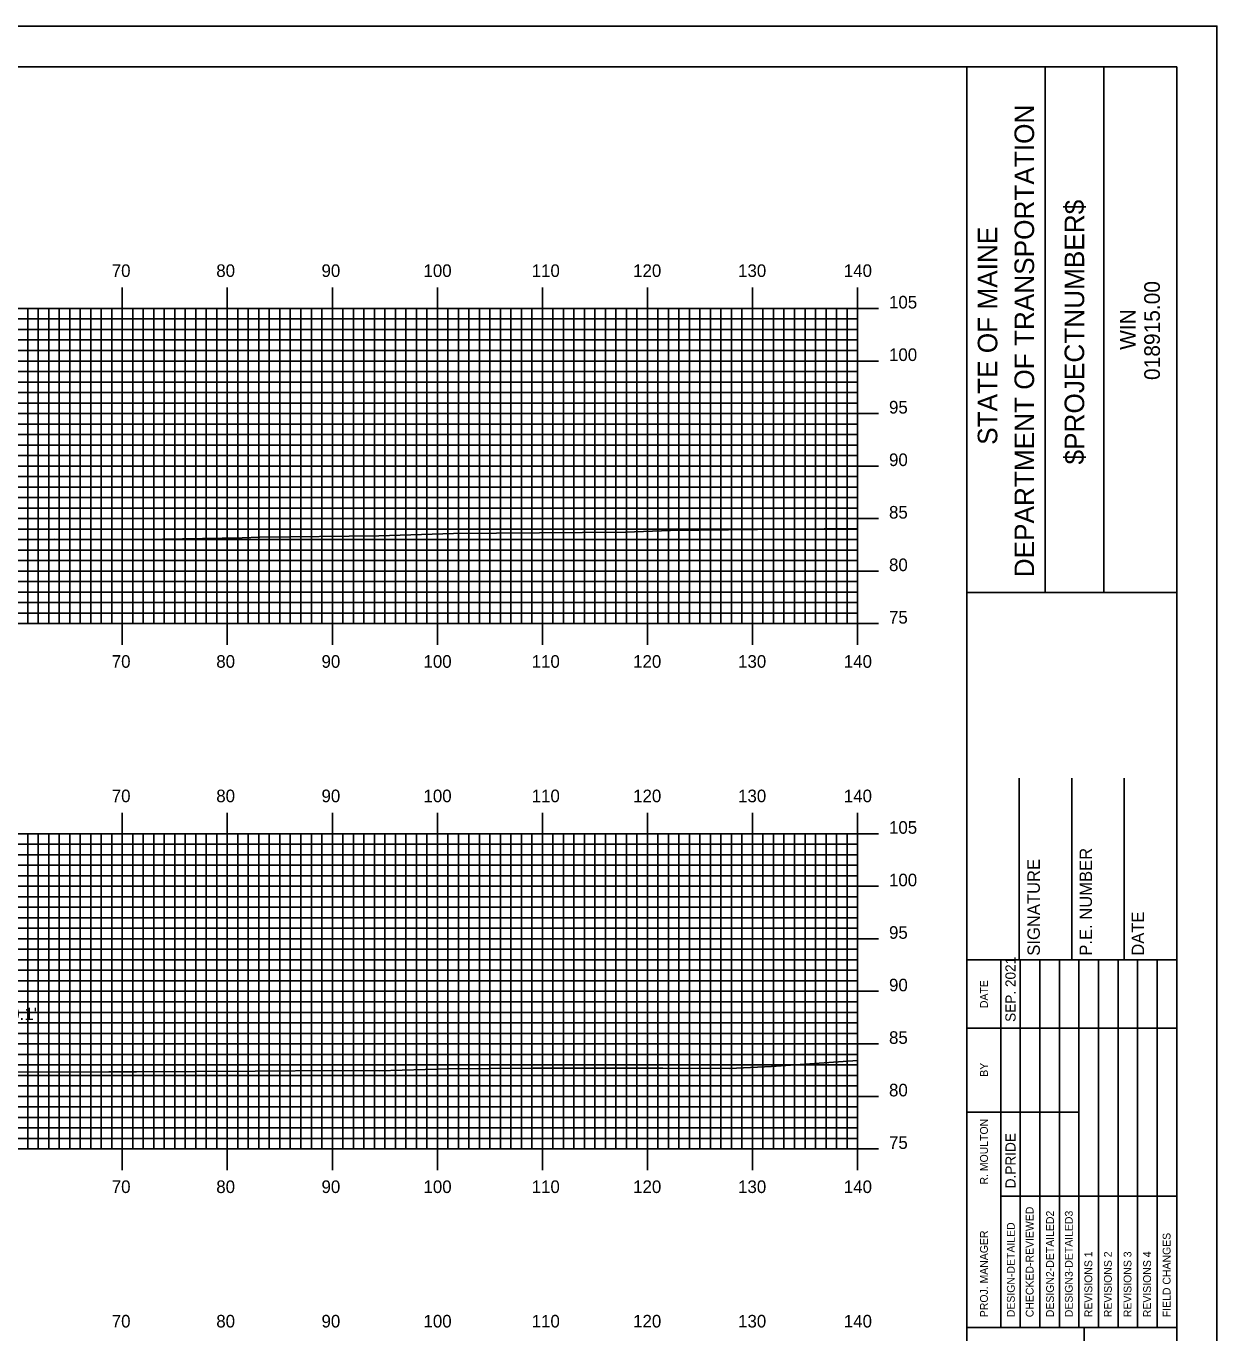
# Model space of a CAD drawing. Extents: x 1757462 to 1757806, y 442591 to 442811.
# Drawn here: x 1757689 to 1757802.3, y 442686.2 to 442810.5 of the extents above; entities that cross this region are included whole.
import ezdxf

# ---------------------------------------------------------------- set-up
doc = ezdxf.new("R2010")
doc.units = 0
for name, color, linetype in [('BORDER', 7, 'Continuous'), ('D_Text_Standard', 7, 'Continuous'), ('H_V ANNOTATION', 7, 'Continuous'), ('MAJOR', 7, 'Continuous'), ('MINOR', 7, 'Continuous'), ('PLOT BOUNDARY', 7, 'Continuous'), ('S_Roadway_Centerline', 7, 'Continuous')]:
    doc.layers.add(name, color=color, linetype=linetype)

msp = doc.modelspace()

# ---------------------------------------------------------------- linework, layer by layer
at = {"layer": 'BORDER'}
for p, q in [((1757778.51, 442596.67), (1757778.51, 442806.67)), ((1757785.97, 442756.66), (1757785.97, 442806.66)), ((1757791.56, 442756.66), (1757791.56, 442806.66)), ((1757778.51, 442756.65), (1757798.51, 442756.65)), ((1757783.51, 442721.67), (1757783.51, 442738.97)), ((1757788.51, 442721.67), (1757788.51, 442738.97)), ((1757793.51, 442721.67), (1757793.51, 442738.97)), ((1757778.51, 442721.67), (1757798.51, 442721.67)), ((1757778.51, 442686.67), (1757798.51, 442686.67)), ((1757789.69, 442616.67), (1757789.69, 442686.67))]:
    msp.add_line(p, q, dxfattribs=at)
msp.add_lwpolyline([(1757478.51, 442596.67), (1757798.51, 442596.67), (1757798.51, 442806.67), (1757478.51, 442806.67)], close=True, dxfattribs=at)
for points in [[(1757781.74, 442715.17), (1757781.74, 442721.67)], [(1757783.6, 442686.68), (1757783.6, 442721.67)], [(1757785.47, 442721.67), (1757785.47, 442686.68)], [(1757787.33, 442686.68), (1757787.33, 442721.67)], [(1757789.19, 442686.68), (1757789.19, 442721.67)], [(1757791.06, 442686.68), (1757791.06, 442721.67)], [(1757792.92, 442686.68), (1757792.92, 442721.67)], [(1757794.78, 442686.68), (1757794.78, 442721.67)], [(1757796.65, 442686.68), (1757796.65, 442721.67)], [(1757781.74, 442686.68), (1757781.74, 442720.26)], [(1757778.51, 442715.17), (1757798.51, 442715.17)], [(1757778.51, 442707.17), (1757781.74, 442707.17)], [(1757781.74, 442707.17), (1757789.19, 442707.17)], [(1757781.74, 442699.17), (1757798.51, 442699.17)]]:
    msp.add_lwpolyline(points, dxfattribs=at)
at = {"layer": 'MAJOR'}
for p, q in [((1757698.11, 442785.67), (1757698.11, 442783.67)), ((1757708.11, 442785.67), (1757708.11, 442783.67)), ((1757718.11, 442785.67), (1757718.11, 442783.67)), ((1757728.11, 442785.67), (1757728.11, 442783.67)), ((1757738.11, 442785.67), (1757738.11, 442783.67)), ((1757748.11, 442785.67), (1757748.11, 442783.67)), ((1757758.11, 442785.67), (1757758.11, 442783.67)), ((1757768.11, 442785.67), (1757768.11, 442783.67)), ((1757488.11, 442783.67), (1757768.11, 442783.67)), ((1757488.11, 442783.67), (1757768.11, 442783.67)), ((1757698.11, 442753.67), (1757698.11, 442783.67)), ((1757708.11, 442753.67), (1757708.11, 442783.67)), ((1757718.11, 442753.67), (1757718.11, 442783.67)), ((1757728.11, 442753.67), (1757728.11, 442783.67)), ((1757738.11, 442753.67), (1757738.11, 442783.67)), ((1757748.11, 442753.67), (1757748.11, 442783.67)), ((1757758.11, 442753.67), (1757758.11, 442783.67)), ((1757770.11, 442783.67), (1757766.11, 442783.67)), ((1757768.11, 442753.67), (1757768.11, 442783.67)), ((1757768.11, 442753.67), (1757768.11, 442783.67)), ((1757488.11, 442778.67), (1757768.11, 442778.67)), ((1757770.11, 442778.67), (1757766.11, 442778.67)), ((1757488.11, 442773.67), (1757768.11, 442773.67)), ((1757770.11, 442773.67), (1757766.11, 442773.67)), ((1757488.11, 442768.67), (1757768.11, 442768.67)), ((1757770.11, 442768.67), (1757766.11, 442768.67)), ((1757488.11, 442763.67), (1757768.11, 442763.67)), ((1757770.11, 442763.67), (1757766.11, 442763.67)), ((1757488.11, 442758.67), (1757768.11, 442758.67)), ((1757770.11, 442758.67), (1757766.11, 442758.67)), ((1757488.11, 442753.67), (1757768.11, 442753.67)), ((1757488.11, 442753.67), (1757768.11, 442753.67)), ((1757698.11, 442751.66), (1757698.11, 442753.67)), ((1757708.11, 442751.66), (1757708.11, 442753.67)), ((1757718.11, 442751.66), (1757718.11, 442753.67)), ((1757728.11, 442751.66), (1757728.11, 442753.67)), ((1757738.11, 442751.66), (1757738.11, 442753.67)), ((1757748.11, 442751.66), (1757748.11, 442753.67)), ((1757758.11, 442751.66), (1757758.11, 442753.67)), ((1757770.11, 442753.67), (1757766.11, 442753.67)), ((1757768.11, 442751.66), (1757768.11, 442753.67)), ((1757698.11, 442735.67), (1757698.11, 442733.67)), ((1757708.11, 442735.67), (1757708.11, 442733.67)), ((1757718.11, 442735.67), (1757718.11, 442733.67)), ((1757728.11, 442735.67), (1757728.11, 442733.67)), ((1757738.11, 442735.67), (1757738.11, 442733.67)), ((1757748.11, 442735.67), (1757748.11, 442733.67)), ((1757758.11, 442735.67), (1757758.11, 442733.67)), ((1757768.11, 442735.67), (1757768.11, 442733.67)), ((1757488.11, 442733.67), (1757768.11, 442733.67)), ((1757488.11, 442733.67), (1757768.11, 442733.67)), ((1757698.11, 442703.67), (1757698.11, 442733.67)), ((1757708.11, 442703.67), (1757708.11, 442733.67)), ((1757718.11, 442703.67), (1757718.11, 442733.67)), ((1757728.11, 442703.67), (1757728.11, 442733.67)), ((1757738.11, 442703.67), (1757738.11, 442733.67)), ((1757748.11, 442703.67), (1757748.11, 442733.67)), ((1757758.11, 442703.67), (1757758.11, 442733.67)), ((1757770.11, 442733.67), (1757766.11, 442733.67)), ((1757768.11, 442703.67), (1757768.11, 442733.67)), ((1757768.11, 442703.67), (1757768.11, 442733.67)), ((1757488.11, 442728.67), (1757768.11, 442728.67)), ((1757770.11, 442728.67), (1757766.11, 442728.67)), ((1757488.11, 442723.67), (1757768.11, 442723.67)), ((1757770.11, 442723.67), (1757766.11, 442723.67)), ((1757488.11, 442718.67), (1757768.11, 442718.67)), ((1757770.11, 442718.67), (1757766.11, 442718.67)), ((1757488.11, 442713.67), (1757768.11, 442713.67)), ((1757770.11, 442713.67), (1757766.11, 442713.67)), ((1757488.11, 442708.67), (1757768.11, 442708.67)), ((1757770.11, 442708.67), (1757766.11, 442708.67)), ((1757488.11, 442703.67), (1757768.11, 442703.67)), ((1757488.11, 442703.67), (1757768.11, 442703.67)), ((1757698.11, 442701.66), (1757698.11, 442703.67)), ((1757708.11, 442701.66), (1757708.11, 442703.67)), ((1757718.11, 442701.66), (1757718.11, 442703.67)), ((1757728.11, 442701.66), (1757728.11, 442703.67)), ((1757738.11, 442701.66), (1757738.11, 442703.67)), ((1757748.11, 442701.66), (1757748.11, 442703.67)), ((1757758.11, 442701.66), (1757758.11, 442703.67)), ((1757770.11, 442703.67), (1757766.11, 442703.67)), ((1757768.11, 442701.66), (1757768.11, 442703.67))]:
    msp.add_line(p, q, dxfattribs=at)
at = {"layer": 'MINOR'}
for p, q in [((1757689.11, 442753.67), (1757689.11, 442783.67)), ((1757690.11, 442753.67), (1757690.11, 442783.67)), ((1757691.11, 442753.67), (1757691.11, 442783.67)), ((1757692.11, 442753.67), (1757692.11, 442783.67)), ((1757693.11, 442753.67), (1757693.11, 442783.67)), ((1757694.11, 442753.67), (1757694.11, 442783.67)), ((1757695.11, 442753.67), (1757695.11, 442783.67)), ((1757696.11, 442753.67), (1757696.11, 442783.67)), ((1757697.11, 442753.67), (1757697.11, 442783.67)), ((1757699.11, 442753.67), (1757699.11, 442783.67)), ((1757700.11, 442753.67), (1757700.11, 442783.67)), ((1757701.11, 442753.67), (1757701.11, 442783.67)), ((1757702.11, 442753.67), (1757702.11, 442783.67)), ((1757703.11, 442753.67), (1757703.11, 442783.67)), ((1757704.11, 442753.67), (1757704.11, 442783.67)), ((1757705.11, 442753.67), (1757705.11, 442783.67)), ((1757706.11, 442753.67), (1757706.11, 442783.67)), ((1757707.11, 442753.67), (1757707.11, 442783.67)), ((1757709.11, 442753.67), (1757709.11, 442783.67)), ((1757710.11, 442753.67), (1757710.11, 442783.67)), ((1757711.11, 442753.67), (1757711.11, 442783.67)), ((1757712.11, 442753.67), (1757712.11, 442783.67)), ((1757713.11, 442753.67), (1757713.11, 442783.67)), ((1757714.11, 442753.67), (1757714.11, 442783.67)), ((1757715.11, 442753.67), (1757715.11, 442783.67)), ((1757716.11, 442753.67), (1757716.11, 442783.67)), ((1757717.11, 442753.67), (1757717.11, 442783.67)), ((1757719.11, 442753.67), (1757719.11, 442783.67)), ((1757720.11, 442753.67), (1757720.11, 442783.67)), ((1757721.11, 442753.67), (1757721.11, 442783.67)), ((1757722.11, 442753.67), (1757722.11, 442783.67)), ((1757723.11, 442753.67), (1757723.11, 442783.67)), ((1757724.11, 442753.67), (1757724.11, 442783.67)), ((1757725.11, 442753.67), (1757725.11, 442783.67)), ((1757726.11, 442753.67), (1757726.11, 442783.67)), ((1757727.11, 442753.67), (1757727.11, 442783.67)), ((1757729.11, 442753.67), (1757729.11, 442783.67)), ((1757730.11, 442753.67), (1757730.11, 442783.67)), ((1757731.11, 442753.67), (1757731.11, 442783.67)), ((1757732.11, 442753.67), (1757732.11, 442783.67)), ((1757733.11, 442753.67), (1757733.11, 442783.67)), ((1757734.11, 442753.67), (1757734.11, 442783.67)), ((1757735.11, 442753.67), (1757735.11, 442783.67)), ((1757736.11, 442753.67), (1757736.11, 442783.67)), ((1757737.11, 442753.67), (1757737.11, 442783.67)), ((1757739.11, 442753.67), (1757739.11, 442783.67)), ((1757740.11, 442753.67), (1757740.11, 442783.67)), ((1757741.11, 442753.67), (1757741.11, 442783.67)), ((1757742.11, 442753.67), (1757742.11, 442783.67)), ((1757743.11, 442753.67), (1757743.11, 442783.67)), ((1757744.11, 442753.67), (1757744.11, 442783.67)), ((1757745.11, 442753.67), (1757745.11, 442783.67)), ((1757746.11, 442753.67), (1757746.11, 442783.67)), ((1757747.11, 442753.67), (1757747.11, 442783.67)), ((1757749.11, 442753.67), (1757749.11, 442783.67)), ((1757750.11, 442753.67), (1757750.11, 442783.67)), ((1757751.11, 442753.67), (1757751.11, 442783.67)), ((1757752.11, 442753.67), (1757752.11, 442783.67)), ((1757753.11, 442753.67), (1757753.11, 442783.67)), ((1757754.11, 442753.67), (1757754.11, 442783.67)), ((1757755.11, 442753.67), (1757755.11, 442783.67)), ((1757756.11, 442753.67), (1757756.11, 442783.67)), ((1757757.11, 442753.67), (1757757.11, 442783.67)), ((1757759.11, 442753.67), (1757759.11, 442783.67)), ((1757760.11, 442753.67), (1757760.11, 442783.67)), ((1757761.11, 442753.67), (1757761.11, 442783.67)), ((1757762.11, 442753.67), (1757762.11, 442783.67)), ((1757763.11, 442753.67), (1757763.11, 442783.67)), ((1757764.11, 442753.67), (1757764.11, 442783.67)), ((1757765.11, 442753.67), (1757765.11, 442783.67)), ((1757766.11, 442753.67), (1757766.11, 442783.67)), ((1757767.11, 442753.67), (1757767.11, 442783.67)), ((1757488.11, 442782.67), (1757768.11, 442782.67)), ((1757768.11, 442782.67), (1757766.11, 442782.67)), ((1757488.11, 442781.67), (1757768.11, 442781.67)), ((1757768.11, 442781.67), (1757766.11, 442781.67)), ((1757488.11, 442780.67), (1757768.11, 442780.67)), ((1757768.11, 442780.67), (1757766.11, 442780.67)), ((1757488.11, 442779.67), (1757768.11, 442779.67)), ((1757768.11, 442779.67), (1757766.11, 442779.67)), ((1757488.11, 442777.67), (1757768.11, 442777.67)), ((1757768.11, 442777.67), (1757766.11, 442777.67)), ((1757488.11, 442776.67), (1757768.11, 442776.67)), ((1757768.11, 442776.67), (1757766.11, 442776.67)), ((1757488.11, 442775.67), (1757768.11, 442775.67)), ((1757768.11, 442775.67), (1757766.11, 442775.67)), ((1757488.11, 442774.67), (1757768.11, 442774.67)), ((1757768.11, 442774.67), (1757766.11, 442774.67)), ((1757488.11, 442772.67), (1757768.11, 442772.67)), ((1757768.11, 442772.67), (1757766.11, 442772.67)), ((1757488.11, 442771.67), (1757768.11, 442771.67)), ((1757768.11, 442771.67), (1757766.11, 442771.67)), ((1757488.11, 442770.67), (1757768.11, 442770.67)), ((1757768.11, 442770.67), (1757766.11, 442770.67)), ((1757488.11, 442769.67), (1757768.11, 442769.67)), ((1757768.11, 442769.67), (1757766.11, 442769.67)), ((1757488.11, 442767.67), (1757768.11, 442767.67)), ((1757768.11, 442767.67), (1757766.11, 442767.67)), ((1757488.11, 442766.67), (1757768.11, 442766.67)), ((1757768.11, 442766.67), (1757766.11, 442766.67)), ((1757488.11, 442765.67), (1757768.11, 442765.67)), ((1757768.11, 442765.67), (1757766.11, 442765.67)), ((1757488.11, 442764.67), (1757768.11, 442764.67)), ((1757768.11, 442764.67), (1757766.11, 442764.67)), ((1757488.11, 442762.67), (1757768.11, 442762.67)), ((1757768.11, 442762.67), (1757766.11, 442762.67)), ((1757488.11, 442761.67), (1757768.11, 442761.67)), ((1757768.11, 442761.67), (1757766.11, 442761.67)), ((1757488.11, 442760.67), (1757768.11, 442760.67)), ((1757768.11, 442760.67), (1757766.11, 442760.67)), ((1757488.11, 442759.67), (1757768.11, 442759.67)), ((1757768.11, 442759.67), (1757766.11, 442759.67)), ((1757488.11, 442757.67), (1757768.11, 442757.67)), ((1757768.11, 442757.67), (1757766.11, 442757.67)), ((1757488.11, 442756.67), (1757768.11, 442756.67)), ((1757768.11, 442756.67), (1757766.11, 442756.67)), ((1757488.11, 442755.67), (1757768.11, 442755.67)), ((1757768.11, 442755.67), (1757766.11, 442755.67)), ((1757488.11, 442754.67), (1757768.11, 442754.67)), ((1757768.11, 442754.67), (1757766.11, 442754.67)), ((1757488.11, 442732.67), (1757768.11, 442732.67)), ((1757689.11, 442703.67), (1757689.11, 442733.67)), ((1757690.11, 442703.67), (1757690.11, 442733.67)), ((1757691.11, 442703.67), (1757691.11, 442733.67)), ((1757692.11, 442703.67), (1757692.11, 442733.67)), ((1757693.11, 442703.67), (1757693.11, 442733.67)), ((1757694.11, 442703.67), (1757694.11, 442733.67)), ((1757695.11, 442703.67), (1757695.11, 442733.67)), ((1757696.11, 442703.67), (1757696.11, 442733.67)), ((1757697.11, 442703.67), (1757697.11, 442733.67)), ((1757699.11, 442703.67), (1757699.11, 442733.67)), ((1757700.11, 442703.67), (1757700.11, 442733.67)), ((1757701.11, 442703.67), (1757701.11, 442733.67)), ((1757702.11, 442703.67), (1757702.11, 442733.67)), ((1757703.11, 442703.67), (1757703.11, 442733.67)), ((1757704.11, 442703.67), (1757704.11, 442733.67)), ((1757705.11, 442703.67), (1757705.11, 442733.67)), ((1757706.11, 442703.67), (1757706.11, 442733.67)), ((1757707.11, 442703.67), (1757707.11, 442733.67)), ((1757709.11, 442703.67), (1757709.11, 442733.67)), ((1757710.11, 442703.67), (1757710.11, 442733.67)), ((1757711.11, 442703.67), (1757711.11, 442733.67)), ((1757712.11, 442703.67), (1757712.11, 442733.67)), ((1757713.11, 442703.67), (1757713.11, 442733.67)), ((1757714.11, 442703.67), (1757714.11, 442733.67)), ((1757715.11, 442703.67), (1757715.11, 442733.67)), ((1757716.11, 442703.67), (1757716.11, 442733.67)), ((1757717.11, 442703.67), (1757717.11, 442733.67)), ((1757719.11, 442703.67), (1757719.11, 442733.67)), ((1757720.11, 442703.67), (1757720.11, 442733.67)), ((1757721.11, 442703.67), (1757721.11, 442733.67)), ((1757722.11, 442703.67), (1757722.11, 442733.67)), ((1757723.11, 442703.67), (1757723.11, 442733.67)), ((1757724.11, 442703.67), (1757724.11, 442733.67)), ((1757725.11, 442703.67), (1757725.11, 442733.67)), ((1757726.11, 442703.67), (1757726.11, 442733.67)), ((1757727.11, 442703.67), (1757727.11, 442733.67)), ((1757729.11, 442703.67), (1757729.11, 442733.67)), ((1757730.11, 442703.67), (1757730.11, 442733.67)), ((1757731.11, 442703.67), (1757731.11, 442733.67)), ((1757732.11, 442703.67), (1757732.11, 442733.67)), ((1757733.11, 442703.67), (1757733.11, 442733.67)), ((1757734.11, 442703.67), (1757734.11, 442733.67)), ((1757735.11, 442703.67), (1757735.11, 442733.67)), ((1757736.11, 442703.67), (1757736.11, 442733.67)), ((1757737.11, 442703.67), (1757737.11, 442733.67)), ((1757739.11, 442703.67), (1757739.11, 442733.67)), ((1757740.11, 442703.67), (1757740.11, 442733.67)), ((1757741.11, 442703.67), (1757741.11, 442733.67)), ((1757742.11, 442703.67), (1757742.11, 442733.67)), ((1757743.11, 442703.67), (1757743.11, 442733.67)), ((1757744.11, 442703.67), (1757744.11, 442733.67)), ((1757745.11, 442703.67), (1757745.11, 442733.67)), ((1757746.11, 442703.67), (1757746.11, 442733.67)), ((1757747.11, 442703.67), (1757747.11, 442733.67)), ((1757749.11, 442703.67), (1757749.11, 442733.67)), ((1757750.11, 442703.67), (1757750.11, 442733.67)), ((1757751.11, 442703.67), (1757751.11, 442733.67)), ((1757752.11, 442703.67), (1757752.11, 442733.67)), ((1757753.11, 442703.67), (1757753.11, 442733.67)), ((1757754.11, 442703.67), (1757754.11, 442733.67)), ((1757755.11, 442703.67), (1757755.11, 442733.67)), ((1757756.11, 442703.67), (1757756.11, 442733.67)), ((1757757.11, 442703.67), (1757757.11, 442733.67)), ((1757759.11, 442703.67), (1757759.11, 442733.67)), ((1757760.11, 442703.67), (1757760.11, 442733.67)), ((1757761.11, 442703.67), (1757761.11, 442733.67)), ((1757762.11, 442703.67), (1757762.11, 442733.67)), ((1757763.11, 442703.67), (1757763.11, 442733.67)), ((1757764.11, 442703.67), (1757764.11, 442733.67)), ((1757765.11, 442703.67), (1757765.11, 442733.67)), ((1757766.11, 442703.67), (1757766.11, 442733.67)), ((1757768.11, 442732.67), (1757766.11, 442732.67)), ((1757767.11, 442703.67), (1757767.11, 442733.67)), ((1757488.11, 442731.67), (1757768.11, 442731.67)), ((1757768.11, 442731.67), (1757766.11, 442731.67)), ((1757488.11, 442730.67), (1757768.11, 442730.67)), ((1757768.11, 442730.67), (1757766.11, 442730.67)), ((1757488.11, 442729.67), (1757768.11, 442729.67)), ((1757768.11, 442729.67), (1757766.11, 442729.67)), ((1757488.11, 442727.67), (1757768.11, 442727.67)), ((1757768.11, 442727.67), (1757766.11, 442727.67)), ((1757488.11, 442726.67), (1757768.11, 442726.67)), ((1757768.11, 442726.67), (1757766.11, 442726.67)), ((1757488.11, 442725.67), (1757768.11, 442725.67)), ((1757768.11, 442725.67), (1757766.11, 442725.67)), ((1757488.11, 442724.67), (1757768.11, 442724.67)), ((1757768.11, 442724.67), (1757766.11, 442724.67)), ((1757488.11, 442722.67), (1757768.11, 442722.67)), ((1757768.11, 442722.67), (1757766.11, 442722.67)), ((1757488.11, 442721.67), (1757768.11, 442721.67)), ((1757768.11, 442721.67), (1757766.11, 442721.67)), ((1757488.11, 442720.67), (1757768.11, 442720.67)), ((1757768.11, 442720.67), (1757766.11, 442720.67)), ((1757488.11, 442719.67), (1757768.11, 442719.67)), ((1757768.11, 442719.67), (1757766.11, 442719.67)), ((1757488.11, 442717.67), (1757768.11, 442717.67)), ((1757768.11, 442717.67), (1757766.11, 442717.67)), ((1757488.11, 442716.67), (1757768.11, 442716.67)), ((1757768.11, 442716.67), (1757766.11, 442716.67)), ((1757488.11, 442715.67), (1757768.11, 442715.67)), ((1757768.11, 442715.67), (1757766.11, 442715.67)), ((1757488.11, 442714.67), (1757768.11, 442714.67)), ((1757768.11, 442714.67), (1757766.11, 442714.67)), ((1757488.11, 442712.67), (1757768.11, 442712.67)), ((1757768.11, 442712.67), (1757766.11, 442712.67)), ((1757488.11, 442711.67), (1757768.11, 442711.67)), ((1757768.11, 442711.67), (1757766.11, 442711.67)), ((1757488.11, 442710.67), (1757768.11, 442710.67)), ((1757768.11, 442710.67), (1757766.11, 442710.67)), ((1757488.11, 442709.67), (1757768.11, 442709.67)), ((1757768.11, 442709.67), (1757766.11, 442709.67)), ((1757488.11, 442707.67), (1757768.11, 442707.67)), ((1757488.11, 442706.67), (1757768.11, 442706.67)), ((1757768.11, 442707.67), (1757766.11, 442707.67)), ((1757768.11, 442706.67), (1757766.11, 442706.67)), ((1757488.11, 442705.67), (1757768.11, 442705.67)), ((1757768.11, 442705.67), (1757766.11, 442705.67)), ((1757488.11, 442704.67), (1757768.11, 442704.67)), ((1757768.11, 442704.67), (1757766.11, 442704.67))]:
    msp.add_line(p, q, dxfattribs=at)
at = {"layer": 'PLOT BOUNDARY'}
msp.add_lwpolyline([(1757462.32, 442590.55), (1757802.32, 442590.55), (1757802.32, 442810.55), (1757462.32, 442810.55)], close=True, dxfattribs=at)
at = {"layer": 'S_Roadway_Centerline'}
for points in [[(1757679.59, 442761.55), (1757691.61, 442761.71), (1757698.15, 442761.64), (1757709.51, 442761.85), (1757711.21, 442761.89), (1757722.55, 442762.02), (1757729.66, 442762.25), (1757746.01, 442762.39), (1757750.29, 442762.53), (1757758.6, 442762.63), (1757768.11, 442762.74)], [(1757681.09, 442710.97), (1757696.82, 442711.01), (1757699.45, 442711), (1757710.76, 442711.08), (1757718.41, 442711.13), (1757722.56, 442711.11), (1757729.15, 442711.29), (1757737.23, 442711.36), (1757749.57, 442711.37), (1757755.92, 442711.33), (1757759.91, 442711.5), (1757768.11, 442712.09)]]:
    msp.add_lwpolyline(points, dxfattribs=at)

# ---------------------------------------------------------------- texts
at = {"layer": 'BORDER'}
for s, height, p in [('DEPARTMENT OF TRANSPORTATION', 1.8635, (1757784.92, 442758.08)), ('$PROJECTNUMBER$', 1.8635, (1757789.69, 442768.82)), ('STATE OF MAINE', 1.8635, (1757781.42, 442770.69)), ('018915.00', 1.491, (1757796.9, 442776.86)), ('WIN', 1.491, (1757794.58, 442779.73)), ('P.E. NUMBER', 1.1811, (1757790.43, 442722.06)), ('SIGNATURE', 1.181, (1757785.47, 442722.06)), ('DATE', 1.181, (1757795.39, 442722.06)), ('SEP. 2021', 0.969, (1757783.16, 442715.76)), ('DATE', 0.743, (1757780.52, 442717.08)), ('BY', 0.743, (1757780.52, 442710.54)), ('R. MOULTON', 0.745, (1757780.52, 442700.28)), ('D.PRIDE', 0.969, (1757783.16, 442699.92)), ('CHECKED-REVIEWED', 0.7455, (1757784.87, 442687.65)), ('DESIGN2-DETAILED2', 0.7455, (1757786.81, 442687.65)), ('DESIGN3-DETAILED3', 0.7455, (1757788.6, 442687.65)), ('DESIGN-DETAILED', 0.7455, (1757783.08, 442687.65)), ('PROJ. MANAGER', 0.7455, (1757780.52, 442687.65)), ('FIELD CHANGES', 0.7455, (1757797.91, 442687.65)), ('REVISIONS 1', 0.7455, (1757790.46, 442687.65)), ('REVISIONS 2', 0.7455, (1757792.32, 442687.65)), ('REVISIONS 3', 0.7455, (1757794.19, 442687.65)), ('REVISIONS 4', 0.7455, (1757796.05, 442687.65))]:
    msp.add_text(s, height=height, rotation=90, dxfattribs=at).set_placement(p)
at = {"layer": 'D_Text_Standard'}
msp.add_text("60.1'", height=1.2, dxfattribs=at).set_placement((1757686.55, 442715.93))
at = {"layer": 'H_V ANNOTATION'}
for s, p in [('70', (1757697.11, 442786.67)), ('80', (1757707.06, 442786.67)), ('90', (1757717.08, 442786.67)), ('100', (1757726.79, 442786.67)), ('110', (1757737.09, 442786.67)), ('120', (1757746.75, 442786.67)), ('130', (1757756.74, 442786.67)), ('140', (1757766.81, 442786.67)), ('105', (1757771.11, 442783.67)), ('100', (1757771.11, 442778.67)), ('95', (1757771.11, 442773.67)), ('90', (1757771.11, 442768.67)), ('85', (1757771.11, 442763.67)), ('80', (1757771.11, 442758.67)), ('75', (1757771.11, 442753.67)), ('70', (1757697.11, 442749.47)), ('80', (1757707.06, 442749.47)), ('90', (1757717.08, 442749.47)), ('100', (1757726.79, 442749.47)), ('110', (1757737.09, 442749.47)), ('120', (1757746.75, 442749.47)), ('130', (1757756.74, 442749.47)), ('140', (1757766.81, 442749.47)), ('70', (1757697.11, 442736.67)), ('80', (1757707.06, 442736.67)), ('90', (1757717.08, 442736.67)), ('100', (1757726.79, 442736.67)), ('110', (1757737.09, 442736.67)), ('120', (1757746.75, 442736.67)), ('130', (1757756.74, 442736.67)), ('140', (1757766.81, 442736.67)), ('105', (1757771.11, 442733.67)), ('100', (1757771.11, 442728.67)), ('95', (1757771.11, 442723.67)), ('90', (1757771.11, 442718.67)), ('85', (1757771.11, 442713.67)), ('80', (1757771.11, 442708.67)), ('75', (1757771.11, 442703.67)), ('70', (1757697.11, 442699.47)), ('80', (1757707.06, 442699.47)), ('90', (1757717.08, 442699.47)), ('100', (1757726.79, 442699.47)), ('110', (1757737.09, 442699.47)), ('120', (1757746.75, 442699.47)), ('130', (1757756.74, 442699.47)), ('140', (1757766.81, 442699.47)), ('70', (1757697.11, 442686.67)), ('80', (1757707.06, 442686.67)), ('90', (1757717.08, 442686.67)), ('100', (1757726.79, 442686.67)), ('110', (1757737.09, 442686.67)), ('120', (1757746.75, 442686.67)), ('130', (1757756.74, 442686.67)), ('140', (1757766.81, 442686.67))]:
    msp.add_text(s, height=1.2, dxfattribs=at).set_placement(p)

doc.saveas('drawing.dxf')
